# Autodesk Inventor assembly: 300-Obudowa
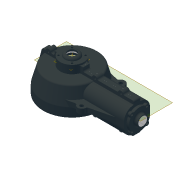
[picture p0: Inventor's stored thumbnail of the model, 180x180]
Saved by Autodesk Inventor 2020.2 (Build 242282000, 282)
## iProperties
Created: 2015-05
Part Number: 300-Obudowa
Document SubType Name: Assembly
Designer: F.Stasiak
Manager: www.cadconsulting.pl
Company: Fabian Stasiak CAD Consulting
Author: F.Stasiak
Subject: Zbiór ćwiczeń. Autodesk Inventor 2020. Kurs podstawowy
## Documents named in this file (5)
- C:\2020_Kurs_podstawowy\R7 Prezentacje\Komponenty\300-Obudowa.iam
- C:\2020_Kurs_podstawowy\R7 Prezentacje\Komponenty\V_123-0010.ipt
- C:\2020_Kurs_podstawowy\R7 Prezentacje\Komponenty\V_123-0070.ipt
- C:\2020_Kurs_podstawowy\R7 Prezentacje\Komponenty\V_123-0060.ipt
- C:\2020_Kurs_podstawowy\R7 Prezentacje\Komponenty\V_123-0020.ipt
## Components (5 placed, 4 different names)
1. 123-0010:1
2. 123-0070:1
3. 123-0070:2
4. 123-0060:1
5. 123-0020:1
